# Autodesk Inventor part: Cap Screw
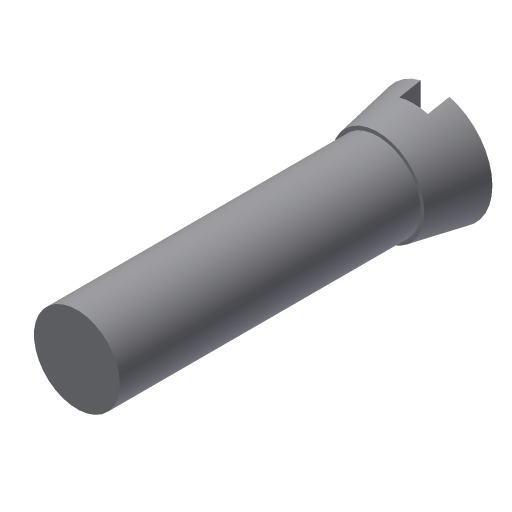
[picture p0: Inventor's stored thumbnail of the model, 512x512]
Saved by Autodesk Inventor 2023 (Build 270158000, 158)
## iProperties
Shininess: 77.0
Length Units: 11269
Angle Units: 11279
Time Units: 11290
Mass Units: 11283
Length Display Precision: 3
Angle Display Precision: 2
Created: 2002-02
Part Number: Cap Screw
Document SubType Name: Modeling
Designer: ***
Density: 1 g/cm^3
Material: Generic
Mass: 0.736586 g
Surface Area: 5.87035 cm^2
Volume: 0.736586 cm^3
Appearance: Default
Density: 0.0
Volumn: 0.0
Area: 0.0
PropertySet Name: Model Information
Control State: 0
Master: False
Checked Out: False
Author: ***
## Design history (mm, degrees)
sketch "Sketch1"
  geometry: L1 (0, 27.83)-(4, 27.83); L2 (4, 27.83)-(3.25, 23.83); L3 (3.25, 23.83)-(0, 23.83); L4 (0, 23.83)-(0, 27.83)
  constraints: 8 end point, 1 horizontal, 1 parallel, 1 perpendicular, 1 point on line
  dimensions: "d2" = 4 distance from line of L1 L2.end; "d5" = 8 diameter of L1.end L4; "d6" = 6.5 diameter of L3.start L4; "d14" = 4 distance of L3.end L1.start
revolve "Revolution1" sketch "Sketch1" stored, may be unused: angle "d7" = 90 deg
sketch "Sketch2"
  geometry: C1 r 3 at (0, 0)
  constraints: 1 centre point
  dimensions: "d8" = 6 diameter of C1
extrude "Extrusion1" join sketch "Sketch2" distance "d9" = 21; taper "d10" = 0 deg
sketch "Sketch3"
  geometry: L1 (-1, 28.967)-(1, 28.967); L2 (1, 28.967)-(1, 26.33); L3 (1, 26.33)-(-1, 26.33); L4 (-1, 26.33)-(-1, 28.967); L5 (-4, 27.83)-(4, 27.83) reference
  constraints: 8 end point, 2 parallel, 1 horizontal, 1 perpendicular
  dimensions: "d11" = 2 distance of L1.start L1.end; "d15" = 1.5 distance between parallel lines of L5 L3
extrude "Extrusion2" cut sketch "Sketch3" extent not by distance; stored distance "d12" = 24; taper "d13" = 0 deg
body "Solid1"
